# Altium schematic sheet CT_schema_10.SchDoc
size 281 x 153 mm
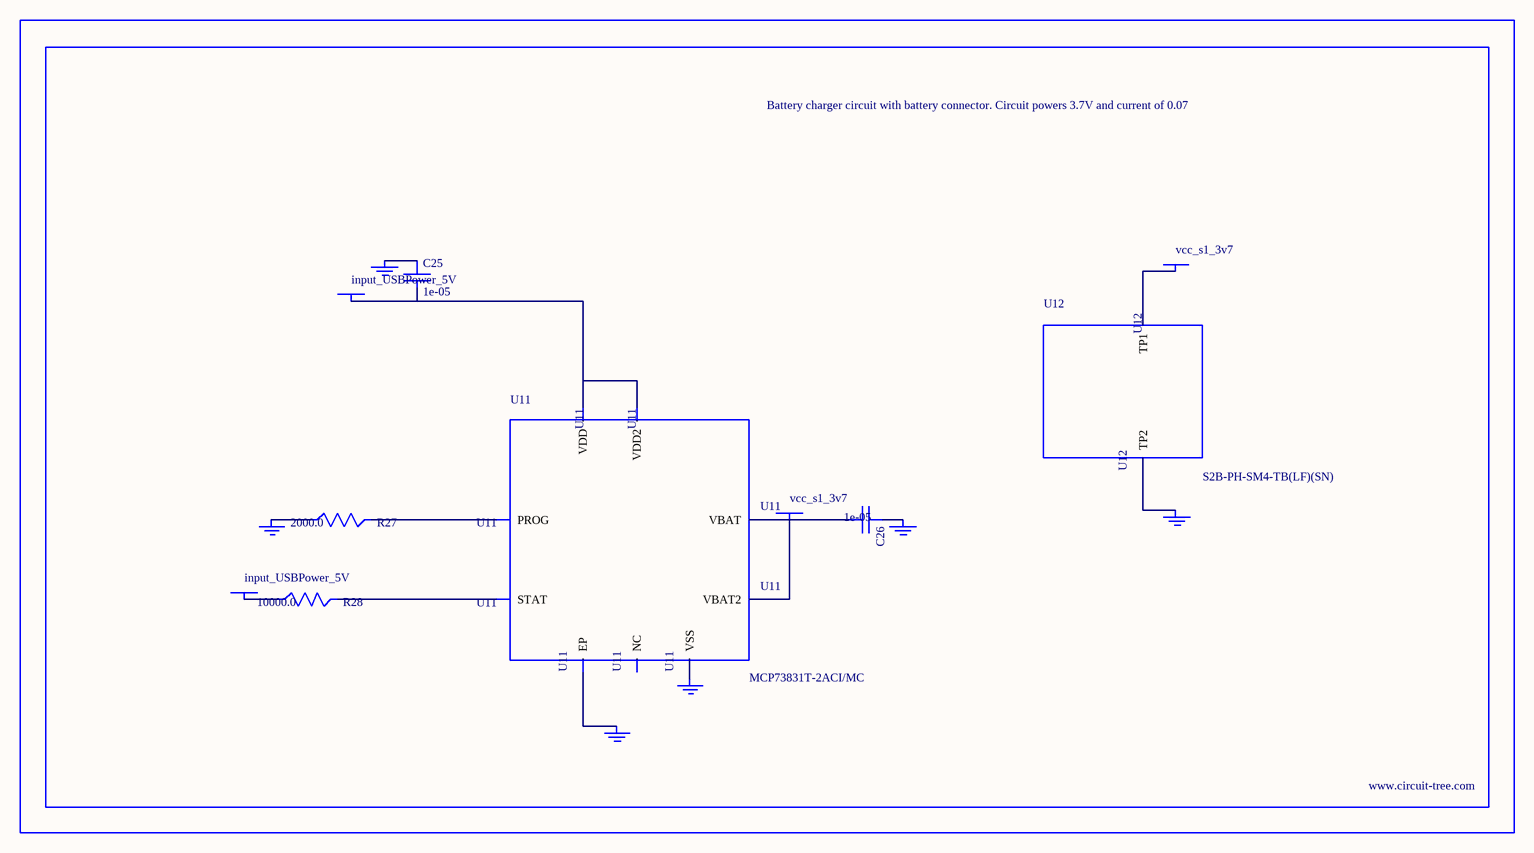
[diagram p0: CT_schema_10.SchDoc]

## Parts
BORDER9  (no value)
C25  1e-05  [C1206]
C26  1e-05  [C1206]
GND_INSTANCE_9_0  (no value)
GND_INSTANCE_9_1  (no value)
GND_INSTANCE_9_2  (no value)
GND_INSTANCE_9_3  (no value)
GND_INSTANCE_9_4  (no value)
GND_INSTANCE_9_5  (no value)
POWER_INSTANCE_9_0  input_USBPower_5V
POWER_INSTANCE_9_1  input_USBPower_5V
POWER_INSTANCE_9_2  vcc_s1_3v7
POWER_INSTANCE_9_3  vcc_s1_3v7
R27  2000.0  [R0603]
R28  10000.0  [R0603]
U11  MCP73831T-2ACI/MC  [DFN8_2X3MC]
U12  S2B-PH-SM4-TB(LF)(SN)  [JST-2-SMD]

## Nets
NetC25_1: C25.1 GND_INSTANCE_9_0.0(GND)
NetC25_2: C25.2 POWER_INSTANCE_9_0.0(PWR) U11.1(VDD) U11.2(VDD2)
NetC26_1: C26.1 GND_INSTANCE_9_1.0(GND)
NetC26_2: C26.2 POWER_INSTANCE_9_2.0(PWR) U11.3(VBAT) U11.4(VBAT2)
NetGND_INSTANCE_9_2_0: GND_INSTANCE_9_2.0(GND) R27.1
NetGND_INSTANCE_9_3_0: GND_INSTANCE_9_3.0(GND) U11.9(EP)
NetGND_INSTANCE_9_4_0: GND_INSTANCE_9_4.0(GND) U11.6(VSS)
NetGND_INSTANCE_9_5_0: GND_INSTANCE_9_5.0(GND) U12.2(TP2)
NetPOWER_INSTANCE_9_1_0: POWER_INSTANCE_9_1.0(PWR) R28.1
NetPOWER_INSTANCE_9_3_0: POWER_INSTANCE_9_3.0(PWR) U12.1(TP1)
NetR27_2: R27.2 U11.8(PROG)
NetR28_2: R28.2 U11.5(STAT)

Not connected (* = marked no-connect by the designer): U11 7(NC)

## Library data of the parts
BORDER9 = BORDER_PAGE9
C25 C26 = C1206C106K3RACTU
GND_INSTANCE_9_0-GND_INSTANCE_9_5 = GND
POWER_INSTANCE_9_0-POWER_INSTANCE_9_3 = PWR
R27 = RC0603JR-072KL
R28 = RC0603JR-0710KL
